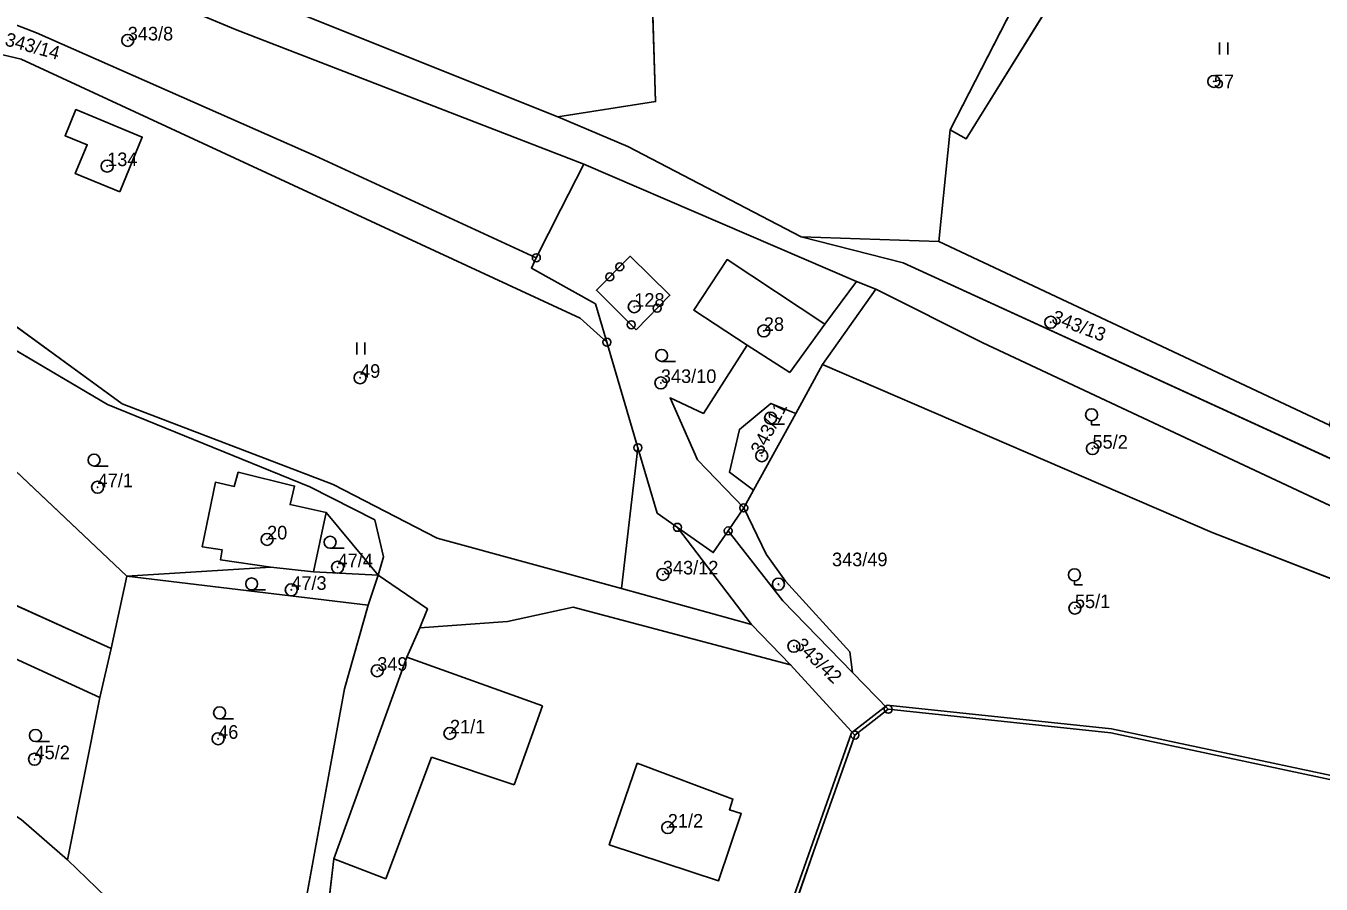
# Model space of a CAD drawing. Extents: x -652854 to -650068, y -1097661 to -1095417.
# Drawn here: x -650503.2 to -650341, y -1096258.8 to -1096151.3 of the extents above; entities that cross this region are included whole.
import ezdxf

# ---------------------------------------------------------------- set-up
doc = ezdxf.new("R2010")
doc.units = 0
for name, color, linetype in [('Definiční body parcel', 7, 'Continuous'), ('Geodetické body', 7, 'Continuous'), ('Hranice - vnitř_ kresba', 7, 'Continuous'), ('Hranice kat_ území', 7, 'Continuous'), ('Hranice parcel', 7, 'Continuous'), ('Obvody jako plochy', 7, 'Continuous'), ('Ostatní hranice', 7, 'Continuous'), ('Parcelní čísla', 7, 'Continuous'), ('Prvky pro prodl_ par_ č_', 7, 'Continuous'), ('Značky kultur', 7, 'Continuous')]:
    doc.layers.add(name, color=color, linetype=linetype)

msp = doc.modelspace()

# ---------------------------------------------------------------- linework, layer by layer
at = {"layer": 'Definiční body parcel'}
for centre, radius in [((-650490.49, -1096153.11), 0.75), ((-650490.49, -1096153.11), 0.0327), ((-650354.44, -1096158.25), 0.75), ((-650354.44, -1096158.25), 0.0327), ((-650493.07, -1096168.86), 0.75), ((-650493.07, -1096168.86), 0.0327), ((-650427.04, -1096186.48), 0.75), ((-650427.04, -1096186.48), 0.0327), ((-650410.81, -1096189.51), 0.75), ((-650374.88, -1096188.43), 0.75), ((-650374.88, -1096188.43), 0.0327), ((-650410.81, -1096189.51), 0.0327), ((-650461.39, -1096195.38), 0.75), ((-650461.39, -1096195.38), 0.0327), ((-650423.71, -1096196.03), 0.75), ((-650423.71, -1096196.03), 0.0327), ((-650411.07, -1096205.15), 0.75), ((-650369.64, -1096204.26), 0.75), ((-650369.64, -1096204.26), 0.0327), ((-650411.07, -1096205.15), 0.0327), ((-650494.27, -1096209.09), 0.75), ((-650494.27, -1096209.09), 0.0327), ((-650473.04, -1096215.63), 0.75), ((-650473.04, -1096215.63), 0.0327), ((-650464.21, -1096219.12), 0.75), ((-650464.21, -1096219.12), 0.0327), ((-650423.46, -1096220.02), 0.75), ((-650470.01, -1096221.95), 0.75), ((-650423.46, -1096220.02), 0.0327), ((-650408.99, -1096221.24), 0.75), ((-650408.99, -1096221.24), 0.0327), ((-650470.01, -1096221.95), 0.0327), ((-650371.84, -1096224.24), 0.75), ((-650371.84, -1096224.24), 0.0327), ((-650407.05, -1096229.02), 0.75), ((-650407.05, -1096229.02), 0.0327), ((-650459.24, -1096232.09), 0.75), ((-650459.24, -1096232.09), 0.0327), ((-650479.17, -1096240.61), 0.75), ((-650479.17, -1096240.61), 0.0327), ((-650450.13, -1096239.94), 0.75), ((-650450.13, -1096239.94), 0.0327), ((-650502.17, -1096243.17), 0.75), ((-650502.17, -1096243.17), 0.0327), ((-650422.84, -1096251.74), 0.75), ((-650422.84, -1096251.74), 0.0327)]:
    msp.add_circle(centre, radius, dxfattribs=at)
at = {"layer": 'Geodetické body'}
for centre, radius in [((-650439.31, -1096180.35), 0.5), ((-650439.31, -1096180.35), 0.001), ((-650430.11, -1096182.74), 0.5), ((-650428.86, -1096181.48), 0.5), ((-650428.86, -1096181.48), 0.001), ((-650430.11, -1096182.74), 0.001), ((-650424.18, -1096186.67), 0.5), ((-650424.18, -1096186.67), 0.001), ((-650427.42, -1096188.74), 0.5), ((-650427.42, -1096188.74), 0.001), ((-650430.47, -1096190.92), 0.5), ((-650430.47, -1096190.92), 0.001), ((-650426.58, -1096204.14), 0.5), ((-650426.58, -1096204.14), 0.001), ((-650413.33, -1096211.68), 0.5), ((-650413.33, -1096211.68), 0.001), ((-650421.64, -1096214.12), 0.5), ((-650421.64, -1096214.12), 0.001), ((-650415.28, -1096214.56), 0.5), ((-650415.28, -1096214.56), 0.001), ((-650395.23, -1096236.92), 0.5), ((-650395.23, -1096236.92), 0.001), ((-650399.41, -1096240.16), 0.5), ((-650399.41, -1096240.16), 0.001)]:
    msp.add_circle(centre, radius, dxfattribs=at)
at = {"layer": 'Hranice - vnitř_ kresba'}
for p, q in [((-650403.18, -1096188.65), (-650407.55, -1096194.72)), ((-650407.55, -1096194.72), (-650412.89, -1096191.29)), ((-650455.52, -1096230.4), (-650438.54, -1096236.47)), ((-650438.54, -1096236.47), (-650442.08, -1096246.38)), ((-650452.45, -1096242.92), (-650458.18, -1096258.17)), ((-650442.08, -1096246.38), (-650452.45, -1096242.92)), ((-650458.18, -1096258.17), (-650464.68, -1096255.67))]:
    msp.add_line(p, q, dxfattribs=at)
at = {"layer": 'Hranice kat_ území'}
for p, q in [((-650396.97, -1096238.27), (-650395.23, -1096236.92)), ((-650367.34, -1096239.87), (-650395.23, -1096236.92)), ((-650399.41, -1096240.16), (-650396.97, -1096238.27)), ((-650399.41, -1096240.16), (-650399.84, -1096241.39)), ((-650338.53, -1096246), (-650367.34, -1096239.87)), ((-650404.57, -1096254.79), (-650399.84, -1096241.39)), ((-650407.37, -1096262.74), (-650404.57, -1096254.79))]:
    msp.add_line(p, q, dxfattribs=at)
at = {"layer": 'Hranice parcel'}
for p, q in [((-650477, -1096151.73), (-650540.89, -1096125.03)), ((-650424.38, -1096160.78), (-650425.11, -1096137.63)), ((-650369.33, -1096139.42), (-650385.46, -1096165.43)), ((-650530.29, -1096141.18), (-650501.92, -1096152.18)), ((-650436.63, -1096162.69), (-650487.47, -1096142.31)), ((-650387.46, -1096164.3), (-650378.74, -1096147.29)), ((-650467.01, -1096167.57), (-650501.92, -1096152.18)), ((-650433.36, -1096168.62), (-650477, -1096151.73)), ((-650433.82, -1096187.93), (-650503.84, -1096155.44)), ((-650436.63, -1096162.69), (-650424.38, -1096160.78)), ((-650496.99, -1096161.78), (-650498.35, -1096165.06)), ((-650488.67, -1096165.22), (-650496.99, -1096161.78)), ((-650427.86, -1096166.41), (-650436.63, -1096162.69)), ((-650387.46, -1096164.3), (-650388.89, -1096178.32)), ((-650385.46, -1096165.43), (-650387.46, -1096164.3)), ((-650498.35, -1096165.06), (-650495.56, -1096166.18)), ((-650491.49, -1096172.1), (-650488.67, -1096165.22)), ((-650495.56, -1096166.18), (-650497.06, -1096169.79)), ((-650467.01, -1096167.57), (-650439.31, -1096180.35)), ((-650406.14, -1096177.7), (-650427.86, -1096166.41)), ((-650433.36, -1096168.62), (-650436.23, -1096174.27)), ((-650399.21, -1096183.32), (-650433.36, -1096168.62)), ((-650497.06, -1096169.79), (-650491.49, -1096172.1)), ((-650491.18, -1096198.65), (-650525.22, -1096173.84)), ((-650436.23, -1096174.27), (-650439.31, -1096180.35)), ((-650493.03, -1096198.73), (-650528.29, -1096177.95)), ((-650406.14, -1096177.7), (-650393.35, -1096180.99)), ((-650388.89, -1096178.32), (-650406.14, -1096177.7)), ((-650339.95, -1096201.3), (-650388.89, -1096178.32)), ((-650439.31, -1096180.35), (-650439.92, -1096181.63)), ((-650427.54, -1096180.15), (-650431.78, -1096184.41)), ((-650422.58, -1096185.03), (-650427.54, -1096180.15)), ((-650419.57, -1096186.92), (-650415.42, -1096180.58)), ((-650415.42, -1096180.58), (-650403.18, -1096188.65)), ((-650439.92, -1096181.63), (-650431.88, -1096186.12)), ((-650393.35, -1096180.99), (-650336.38, -1096207.09)), ((-650403.18, -1096188.65), (-650399.21, -1096183.32)), ((-650396.8, -1096184.29), (-650399.21, -1096183.32)), ((-650431.78, -1096184.41), (-650426.79, -1096189.36)), ((-650426.79, -1096189.36), (-650422.58, -1096185.03)), ((-650396.8, -1096184.29), (-650403.45, -1096193.71)), ((-650383.39, -1096191), (-650396.8, -1096184.29)), ((-650431.88, -1096186.12), (-650430.47, -1096190.92)), ((-650412.89, -1096191.29), (-650419.57, -1096186.92)), ((-650433.82, -1096187.93), (-650430.47, -1096190.92)), ((-650430.47, -1096190.92), (-650426.58, -1096204.14)), ((-650418.37, -1096199.85), (-650412.89, -1096191.29)), ((-650331.19, -1096215.48), (-650383.39, -1096191)), ((-650403.45, -1096193.71), (-650406.82, -1096199.84)), ((-650403.45, -1096193.71), (-650354.65, -1096214.75)), ((-650490.59, -1096220.24), (-650516.09, -1096196.19)), ((-650419.11, -1096205.66), (-650422.55, -1096197.9)), ((-650422.55, -1096197.9), (-650418.37, -1096199.85)), ((-650409.92, -1096198.6), (-650413.88, -1096201.86)), ((-650406.82, -1096199.84), (-650409.92, -1096198.6)), ((-650467.67, -1096209.04), (-650493.03, -1096198.73)), ((-650464.75, -1096208.75), (-650491.18, -1096198.65)), ((-650412.11, -1096209.48), (-650406.82, -1096199.84)), ((-650413.88, -1096201.86), (-650415.12, -1096207.22)), ((-650426.58, -1096204.14), (-650428.64, -1096221.8)), ((-650426.58, -1096204.14), (-650424.16, -1096212.34)), ((-650413.33, -1096211.68), (-650419.11, -1096205.66)), ((-650476.66, -1096207.22), (-650477.15, -1096209)), ((-650469.6, -1096208.96), (-650476.66, -1096207.22)), ((-650415.12, -1096207.22), (-650412.11, -1096209.48)), ((-650479.52, -1096208.46), (-650481.16, -1096216.55)), ((-650477.15, -1096209), (-650479.52, -1096208.46)), ((-650470.15, -1096211.27), (-650469.6, -1096208.96)), ((-650459.55, -1096213.2), (-650467.67, -1096209.04)), ((-650451.74, -1096215.49), (-650464.75, -1096208.75)), ((-650413.33, -1096211.68), (-650412.11, -1096209.48)), ((-650465.63, -1096212.25), (-650470.15, -1096211.27)), ((-650467.24, -1096219.68), (-650465.63, -1096212.25)), ((-650465.63, -1096212.25), (-650459.14, -1096220.1)), ((-650458.47, -1096217.82), (-650459.55, -1096213.2)), ((-650424.16, -1096212.34), (-650421.64, -1096214.12)), ((-650415.28, -1096214.56), (-650413.33, -1096211.68)), ((-650410.5, -1096217.47), (-650413.33, -1096211.68)), ((-650412.37, -1096226.28), (-650421.64, -1096214.12)), ((-650421.64, -1096214.12), (-650417.14, -1096217.29)), ((-650417.14, -1096217.29), (-650415.28, -1096214.56)), ((-650415.28, -1096214.56), (-650408.44, -1096223.31)), ((-650354.65, -1096214.75), (-650333.29, -1096223.06)), ((-650428.64, -1096221.8), (-650451.74, -1096215.49)), ((-650492.59, -1096229.3), (-650518.58, -1096217.54)), ((-650481.16, -1096216.55), (-650478.66, -1096216.95)), ((-650478.66, -1096216.95), (-650478.86, -1096218.21)), ((-650459.14, -1096220.1), (-650458.47, -1096217.82)), ((-650408.09, -1096220.88), (-650410.5, -1096217.47)), ((-650490.59, -1096220.24), (-650472.58, -1096219.1)), ((-650478.86, -1096218.21), (-650472.58, -1096219.1)), ((-650472.58, -1096219.1), (-650467.24, -1096219.68)), ((-650459.14, -1096220.1), (-650467.24, -1096219.68)), ((-650492.59, -1096229.3), (-650490.59, -1096220.24)), ((-650490.59, -1096220.24), (-650460.37, -1096223.86)), ((-650459.14, -1096220.1), (-650460.37, -1096223.86)), ((-650452.93, -1096224.35), (-650459.14, -1096220.1)), ((-650400.02, -1096229.73), (-650408.09, -1096220.88)), ((-650428.64, -1096221.8), (-650412.37, -1096226.28)), ((-650460.37, -1096223.86), (-650463.36, -1096234.36)), ((-650453.89, -1096226.7), (-650452.93, -1096224.35)), ((-650442.93, -1096225.91), (-650434.71, -1096224.14)), ((-650434.71, -1096224.14), (-650407.47, -1096231.34)), ((-650408.44, -1096223.31), (-650399.71, -1096232.3)), ((-650453.89, -1096226.7), (-650442.93, -1096225.91)), ((-650455.52, -1096230.4), (-650453.89, -1096226.7)), ((-650407.47, -1096231.34), (-650412.37, -1096226.28)), ((-650493.99, -1096235.45), (-650492.59, -1096229.3)), ((-650505.2, -1096230.31), (-650493.99, -1096235.45)), ((-650464.68, -1096255.67), (-650455.52, -1096230.4)), ((-650399.71, -1096232.3), (-650400.02, -1096229.73)), ((-650399.41, -1096240.16), (-650407.47, -1096231.34)), ((-650395.23, -1096236.92), (-650399.71, -1096232.3)), ((-650498.02, -1096255.76), (-650493.99, -1096235.45)), ((-650463.36, -1096234.36), (-650469.56, -1096268.42)), ((-650426.69, -1096243.68), (-650430.17, -1096253.88)), ((-650426.69, -1096243.68), (-650414.69, -1096248.16)), ((-650415.12, -1096249.5), (-650414.69, -1096248.16)), ((-650416.48, -1096258.39), (-650413.65, -1096249.98)), ((-650413.65, -1096249.98), (-650415.12, -1096249.5)), ((-650503.86, -1096250.74), (-650498.02, -1096255.76)), ((-650430.17, -1096253.88), (-650416.48, -1096258.39)), ((-650493.19, -1096260.46), (-650498.02, -1096255.76)), ((-650466.25, -1096269.05), (-650464.68, -1096255.67))]:
    msp.add_line(p, q, dxfattribs=at)
at = {"layer": 'Obvody jako plochy'}
for points in [[(-650359.66, -1096092.86), (-650371.98, -1096120.86), (-650385.1, -1096138.24), (-650425.11, -1096137.63), (-650424.38, -1096160.78), (-650436.63, -1096162.69), (-650427.86, -1096166.41), (-650406.14, -1096177.7), (-650388.89, -1096178.32), (-650387.46, -1096164.3), (-650378.74, -1096147.29), (-650366.63, -1096122.44), (-650349.82, -1096108.97), (-650336.31, -1096106.56), (-650321.49, -1096079.73), (-650306.07, -1096059.44), (-650308.82, -1096057.97), (-650324.94, -1096066.56), (-650338.43, -1096059.48)], [(-650306.07, -1096059.44), (-650321.49, -1096079.73), (-650336.31, -1096106.56), (-650349.82, -1096108.97), (-650366.63, -1096122.44), (-650378.74, -1096147.29), (-650387.46, -1096164.3), (-650385.46, -1096165.43), (-650369.33, -1096139.42), (-650359.36, -1096126.99), (-650343.09, -1096117.09), (-650314.38, -1096148.79), (-650291.47, -1096114.19), (-650280.75, -1096101.19)], [(-650433.36, -1096168.62), (-650477, -1096151.73), (-650540.89, -1096125.03), (-650563.99, -1096115.37), (-650568.37, -1096118.51), (-650556.56, -1096122.07), (-650548.54, -1096129.44), (-650544.44, -1096132.62), (-650530.29, -1096141.18), (-650501.92, -1096152.18), (-650467.01, -1096167.57), (-650439.31, -1096180.35), (-650436.23, -1096174.27)], [(-650339.95, -1096201.3), (-650338.09, -1096193.93), (-650324.6, -1096168.25), (-650314.38, -1096148.79), (-650343.09, -1096117.09), (-650359.36, -1096126.99), (-650369.33, -1096139.42), (-650385.46, -1096165.43), (-650387.46, -1096164.3), (-650388.89, -1096178.32)], [(-650425.11, -1096137.63), (-650433.69, -1096137.29), (-650503.38, -1096122.58), (-650504.25, -1096126.33), (-650485.01, -1096136.73), (-650487.47, -1096142.31), (-650436.63, -1096162.69), (-650424.38, -1096160.78)], [(-650430.47, -1096190.92), (-650433.82, -1096187.93), (-650503.84, -1096155.44), (-650515.4, -1096152.75), (-650524.77, -1096172.87), (-650525.22, -1096173.84), (-650491.18, -1096198.65), (-650464.75, -1096208.75), (-650451.74, -1096215.49), (-650428.64, -1096221.8), (-650426.58, -1096204.14)], [(-650491.49, -1096172.1), (-650497.06, -1096169.79), (-650495.56, -1096166.18), (-650498.35, -1096165.06), (-650496.99, -1096161.78), (-650488.67, -1096165.22)], [(-650491.49, -1096172.1), (-650488.67, -1096165.22), (-650496.99, -1096161.78), (-650498.35, -1096165.06), (-650495.56, -1096166.18), (-650497.06, -1096169.79)], [(-650439.92, -1096181.63), (-650431.88, -1096186.12), (-650430.47, -1096190.92), (-650426.58, -1096204.14), (-650424.16, -1096212.34), (-650421.64, -1096214.12), (-650417.14, -1096217.29), (-650415.28, -1096214.56), (-650413.33, -1096211.68), (-650419.11, -1096205.66), (-650422.55, -1096197.9), (-650418.37, -1096199.85), (-650412.89, -1096191.29), (-650419.57, -1096186.92), (-650415.42, -1096180.58), (-650403.18, -1096188.65), (-650399.21, -1096183.32), (-650433.36, -1096168.62), (-650436.23, -1096174.27), (-650439.31, -1096180.35)], [(-650490.59, -1096220.24), (-650472.58, -1096219.1), (-650478.86, -1096218.21), (-650478.66, -1096216.95), (-650481.16, -1096216.55), (-650479.52, -1096208.46), (-650477.15, -1096209), (-650476.66, -1096207.22), (-650469.6, -1096208.96), (-650470.15, -1096211.27), (-650465.63, -1096212.25), (-650459.14, -1096220.1), (-650458.47, -1096217.82), (-650459.55, -1096213.2), (-650467.67, -1096209.04), (-650493.03, -1096198.73), (-650528.29, -1096177.95), (-650528.77, -1096178.83), (-650533.62, -1096187.74), (-650525.13, -1096192.93), (-650516.09, -1096196.19)], [(-650339.95, -1096201.3), (-650388.89, -1096178.32), (-650406.14, -1096177.7), (-650393.35, -1096180.99), (-650336.38, -1096207.09), (-650338.58, -1096203.52), (-650339.42, -1096202.16)], [(-650426.79, -1096189.36), (-650431.78, -1096184.41), (-650427.54, -1096180.15), (-650422.58, -1096185.03)], [(-650426.79, -1096189.36), (-650422.58, -1096185.03), (-650427.54, -1096180.15), (-650431.78, -1096184.41)], [(-650403.45, -1096193.71), (-650396.8, -1096184.29), (-650399.21, -1096183.32), (-650403.18, -1096188.65), (-650415.42, -1096180.58), (-650419.57, -1096186.92), (-650412.89, -1096191.29), (-650418.37, -1096199.85), (-650422.55, -1096197.9), (-650419.11, -1096205.66), (-650413.33, -1096211.68), (-650412.11, -1096209.48), (-650415.12, -1096207.22), (-650413.88, -1096201.86), (-650409.92, -1096198.6), (-650406.82, -1096199.84)], [(-650403.45, -1096193.71), (-650354.65, -1096214.75), (-650333.29, -1096223.06), (-650333.02, -1096222.34), (-650331.19, -1096215.48), (-650383.39, -1096191), (-650396.8, -1096184.29)], [(-650518.58, -1096217.54), (-650492.59, -1096229.3), (-650490.59, -1096220.24), (-650516.09, -1096196.19), (-650525.13, -1096192.93), (-650525.98, -1096194.97), (-650531.08, -1096208.33), (-650533.58, -1096213.94), (-650540.25, -1096229.11), (-650527.08, -1096236.47)], [(-650403.45, -1096193.71), (-650406.82, -1096199.84), (-650412.11, -1096209.48), (-650413.33, -1096211.68), (-650410.5, -1096217.47), (-650408.09, -1096220.88), (-650400.02, -1096229.73), (-650399.71, -1096232.3), (-650395.23, -1096236.92), (-650367.34, -1096239.87), (-650338.53, -1096246), (-650338.27, -1096244.35), (-650336.18, -1096230.94), (-650333.29, -1096223.06), (-650354.65, -1096214.75)], [(-650406.82, -1096199.84), (-650409.92, -1096198.6), (-650413.88, -1096201.86), (-650415.12, -1096207.22), (-650412.11, -1096209.48)], [(-650426.58, -1096204.14), (-650428.64, -1096221.8), (-650412.37, -1096226.28), (-650421.64, -1096214.12), (-650424.16, -1096212.34)], [(-650472.58, -1096219.1), (-650467.24, -1096219.68), (-650465.63, -1096212.25), (-650470.15, -1096211.27), (-650469.6, -1096208.96), (-650476.66, -1096207.22), (-650477.15, -1096209), (-650479.52, -1096208.46), (-650481.16, -1096216.55), (-650478.66, -1096216.95), (-650478.86, -1096218.21)], [(-650467.24, -1096219.68), (-650459.14, -1096220.1), (-650465.63, -1096212.25)], [(-650399.71, -1096232.3), (-650400.02, -1096229.73), (-650408.09, -1096220.88), (-650410.5, -1096217.47), (-650413.33, -1096211.68), (-650415.28, -1096214.56), (-650408.44, -1096223.31)], [(-650408.44, -1096223.31), (-650415.28, -1096214.56), (-650417.14, -1096217.29), (-650421.64, -1096214.12), (-650412.37, -1096226.28), (-650407.47, -1096231.34), (-650399.41, -1096240.16), (-650396.97, -1096238.27), (-650395.23, -1096236.92), (-650399.71, -1096232.3)], [(-650518.58, -1096217.54), (-650527.08, -1096236.47), (-650518.43, -1096241.37), (-650516.15, -1096235.97), (-650509.05, -1096239.03), (-650505.2, -1096230.31), (-650493.99, -1096235.45), (-650492.59, -1096229.3)], [(-650490.59, -1096220.24), (-650460.37, -1096223.86), (-650459.14, -1096220.1), (-650467.24, -1096219.68), (-650472.58, -1096219.1)], [(-650469.56, -1096268.42), (-650463.36, -1096234.36), (-650460.37, -1096223.86), (-650490.59, -1096220.24), (-650492.59, -1096229.3), (-650493.99, -1096235.45), (-650498.02, -1096255.76), (-650493.19, -1096260.46), (-650481.8, -1096266.43)], [(-650466.25, -1096269.05), (-650464.68, -1096255.67), (-650455.52, -1096230.4), (-650453.89, -1096226.7), (-650452.93, -1096224.35), (-650459.14, -1096220.1), (-650460.37, -1096223.86), (-650463.36, -1096234.36), (-650469.56, -1096268.42)], [(-650413.62, -1096280.45), (-650407.37, -1096262.74), (-650404.57, -1096254.79), (-650399.84, -1096241.39), (-650399.41, -1096240.16), (-650407.47, -1096231.34), (-650434.71, -1096224.14), (-650442.93, -1096225.91), (-650453.89, -1096226.7), (-650455.52, -1096230.4), (-650464.68, -1096255.67), (-650466.25, -1096269.05), (-650437.69, -1096272.85)], [(-650503.86, -1096250.74), (-650498.02, -1096255.76), (-650493.99, -1096235.45), (-650505.2, -1096230.31), (-650509.05, -1096239.03), (-650516.15, -1096235.97), (-650518.43, -1096241.37)], [(-650426.69, -1096243.68), (-650414.69, -1096248.16), (-650415.12, -1096249.5), (-650413.65, -1096249.98), (-650416.48, -1096258.39), (-650430.17, -1096253.88)], [(-650426.69, -1096243.68), (-650430.17, -1096253.88), (-650416.48, -1096258.39), (-650413.65, -1096249.98), (-650415.12, -1096249.5), (-650414.69, -1096248.16)]]:
    msp.add_lwpolyline(points, close=True, dxfattribs=at)
for points in [[(-650336.38, -1096207.09), (-650393.35, -1096180.99), (-650406.14, -1096177.7), (-650427.86, -1096166.41), (-650436.63, -1096162.69), (-650487.47, -1096142.31), (-650543.65, -1096119.5)], [(-650540.89, -1096125.03), (-650477, -1096151.73), (-650433.36, -1096168.62), (-650399.21, -1096183.32), (-650396.8, -1096184.29), (-650383.39, -1096191), (-650331.19, -1096215.48)], [(-650503.84, -1096155.44), (-650433.82, -1096187.93), (-650430.47, -1096190.92), (-650431.88, -1096186.12), (-650439.92, -1096181.63), (-650439.31, -1096180.35), (-650467.01, -1096167.57), (-650501.92, -1096152.18), (-650530.29, -1096141.18)], [(-650528.29, -1096177.95), (-650493.03, -1096198.73), (-650467.67, -1096209.04), (-650459.55, -1096213.2), (-650458.47, -1096217.82), (-650459.14, -1096220.1), (-650452.93, -1096224.35), (-650453.89, -1096226.7), (-650442.93, -1096225.91), (-650434.71, -1096224.14), (-650407.47, -1096231.34), (-650412.37, -1096226.28), (-650428.64, -1096221.8), (-650451.74, -1096215.49), (-650464.75, -1096208.75), (-650491.18, -1096198.65), (-650525.22, -1096173.84)], [(-650493.19, -1096260.46), (-650498.02, -1096255.76), (-650503.86, -1096250.74)]]:
    msp.add_lwpolyline(points, dxfattribs=at)
at = {"layer": 'Ostatní hranice'}
for p, q in [((-650395.35, -1096236.39), (-650399.84, -1096239.85)), ((-650367.27, -1096239.37), (-650395.35, -1096236.39)), ((-650399.84, -1096239.85), (-650414.14, -1096280.39)), ((-650338.95, -1096245.39), (-650367.27, -1096239.37))]:
    msp.add_line(p, q, dxfattribs=at)
at = {"layer": 'Značky kultur'}
for p, q in [((-650353.727, -1096153.375), (-650353.727, -1096154.875)), ((-650352.705, -1096154.875), (-650352.705, -1096153.375)), ((-650461.807, -1096190.945), (-650461.807, -1096192.445)), ((-650460.785, -1096192.445), (-650460.785, -1096190.945)), ((-650421.86, -1096193.33), (-650423.61, -1096193.33)), ((-650408.22, -1096201.18), (-650409.97, -1096201.18)), ((-650369.76, -1096200.76), (-650369.76, -1096201.26)), ((-650369.76, -1096201.26), (-650368.737, -1096201.26)), ((-650492.96, -1096206.44), (-650494.71, -1096206.44)), ((-650463.39, -1096216.74), (-650465.14, -1096216.74)), ((-650371.9, -1096220.82), (-650371.9, -1096221.32)), ((-650371.9, -1096221.32), (-650370.877, -1096221.32)), ((-650473.22, -1096221.95), (-650474.97, -1096221.95)), ((-650477.23, -1096238.11), (-650478.98, -1096238.11)), ((-650500.3, -1096240.95), (-650502.05, -1096240.95))]:
    msp.add_line(p, q, dxfattribs=at)
for centre in [(-650423.61, -1096192.58), (-650409.97, -1096200.43), (-650369.76, -1096200.01), (-650494.71, -1096205.69), (-650465.14, -1096215.99), (-650371.9, -1096220.07), (-650474.97, -1096221.2), (-650478.98, -1096237.36), (-650502.05, -1096240.2)]:
    msp.add_circle(centre, 0.75, dxfattribs=at)

# ---------------------------------------------------------------- texts
at = {"layer": 'Parcelní čísla'}
for s, p in [('343/8', (-650490.49, -1096153.11)), ('57', (-650354.44, -1096159.1)), ('134', (-650493.07, -1096168.86)), ('128', (-650427.04, -1096186.48)), ('28', (-650410.81, -1096189.51)), ('49', (-650461.39, -1096195.38)), ('343/10', (-650423.71, -1096196.03)), ('55/2', (-650369.64, -1096204.26)), ('47/1', (-650494.27, -1096209.09)), ('20', (-650473.04, -1096215.63)), ('47/4', (-650464.21, -1096219.12)), ('343/12', (-650423.46, -1096220.02)), ('47/3', (-650470.01, -1096221.95)), ('55/1', (-650371.84, -1096224.24)), ('349', (-650459.24, -1096232.09)), ('46', (-650479.17, -1096240.61)), ('21/1', (-650450.13, -1096239.94)), ('45/2', (-650502.17, -1096243.17)), ('21/2', (-650422.84, -1096251.74))]:
    msp.add_text(s, height=1.7, dxfattribs=at).set_placement(p)
for s, height, rotation, p in [('343/14', 1.7, 344.574, (-650505.99, -1096153.71)), ('343/13', 1.7, 339.444, (-650374.88, -1096188.43)), ('343/11', 1.7, 62.19, (-650411.07, -1096205.15)), ('343/49', 0.1, 310.122, (-650408.99, -1096221.24)), ('343/42', 1.7, 316.098, (-650407.05, -1096229.02))]:
    msp.add_text(s, height=height, rotation=rotation, dxfattribs=at).set_placement(p)
at = {"layer": 'Prvky pro prodl_ par_ č_'}
msp.add_text('343/49', height=1.7, dxfattribs=at).set_placement((-650402.27, -1096218.99))

doc.saveas('drawing.dxf')
